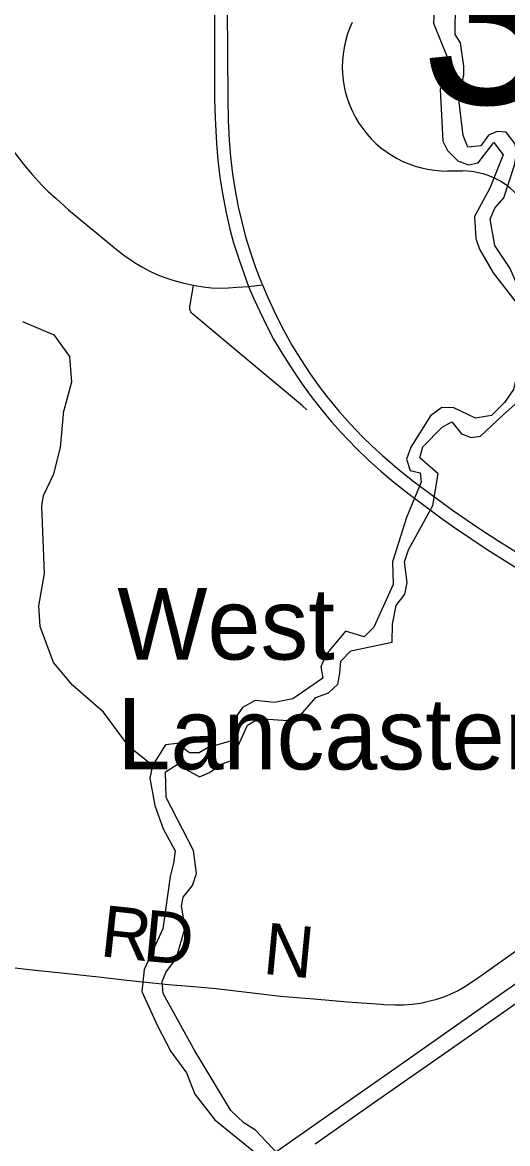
# Model space of a CAD drawing. Extents: x -49 to -8.2, y 9.4 to 23.5.
# Drawn here: x -41.395 to -41.126, y 17.238 to 17.858 of the extents above; entities that cross this region are included whole.
import ezdxf

# ---------------------------------------------------------------- set-up
doc = ezdxf.new("R2010")
doc.units = 0
for name, color, linetype in [('GM_X_County_Road', 7, 'Continuous'), ('GM_X_Interstate_Route', 7, 'Continuous'), ('GM_X_Major_River', 7, 'Continuous'), ('GM_X_Minor_River', 7, 'Continuous'), ('GM_X_State_Route', 7, 'Continuous'), ('GM_X_Township_Road', 7, 'Continuous'), ('GM_X_Township_Road_Text', 7, 'Continuous'), ('GM_X_Unincorporated_Text', 7, 'Continuous'), ('GM_X_US_Shield', 7, 'Continuous')]:
    doc.layers.add(name, color=color, linetype=linetype)

msp = doc.modelspace()

# ---------------------------------------------------------------- linework, layer by layer
at = {"layer": 'GM_X_County_Road'}
for points in [[(-41.40101, 17.78872), (-41.39439, 17.78007), (-41.38943, 17.77407), (-41.38416, 17.76832), (-41.38085, 17.76502), (-41.37623, 17.76084), (-41.36927, 17.75463), (-41.35971, 17.74666), (-41.35369, 17.74176), (-41.34292, 17.7328), (-41.338, 17.72897), (-41.33439, 17.72651)], [(-41.33439, 17.72651), (-41.33284, 17.72545), (-41.32882, 17.72304), (-41.32468, 17.72084), (-41.32041, 17.71889), (-41.31605, 17.71719), (-41.3116, 17.71573), (-41.30558, 17.71407), (-41.30025, 17.71289)], [(-41.30025, 17.71289), (-41.29948, 17.71272), (-41.29485, 17.71197), (-41.29019, 17.71151), (-41.28551, 17.71134), (-41.28081, 17.71143), (-41.27614, 17.71176), (-41.26968, 17.71222)], [(-41.26968, 17.71222), (-41.26206, 17.71303)]]:
    msp.add_lwpolyline(points, dxfattribs=at)
at = {"layer": 'GM_X_Interstate_Route'}
for points in [[(-41.23285, 17.23785), (-41.20004, 17.26087), (-41.16107, 17.28809), (-41.09894, 17.33152), (-41.07743, 17.34663), (-41.05165, 17.36473), (-41.02467, 17.38361), (-40.97838, 17.41607), (-40.95038, 17.43567), (-40.94996, 17.43597)], [(-41.25415, 17.23378), (-41.23997, 17.24376), (-41.21333, 17.26237), (-41.18692, 17.28076), (-41.12792, 17.32231), (-41.11945, 17.32829)]]:
    msp.add_lwpolyline(points, dxfattribs=at)
at = {"layer": 'GM_X_Major_River'}
for points in [[(-41.16654, 17.87659), (-41.16739, 17.85782), (-41.15973, 17.83863), (-41.1592, 17.83256), (-41.1638, 17.8212), (-41.16225, 17.79255), (-41.15962, 17.78742), (-41.15397, 17.7817), (-41.14812, 17.77959), (-41.14281, 17.7807), (-41.13405, 17.79185), (-41.12897, 17.78499), (-41.13626, 17.76663), (-41.14467, 17.75093), (-41.14398, 17.73879), (-41.14193, 17.7329), (-41.13442, 17.71978), (-41.12032, 17.70169), (-41.11547, 17.68839), (-41.11493, 17.68289), (-41.11992, 17.67001), (-41.12322, 17.65524), (-41.12817, 17.64805), (-41.13539, 17.64082)], [(-41.14125, 17.78998), (-41.14845, 17.78926), (-41.15106, 17.79572), (-41.15342, 17.81565), (-41.1507, 17.82929), (-41.15067, 17.83403), (-41.1525, 17.84694), (-41.1555, 17.85169), (-41.15522, 17.86857)], [(-41.12932, 17.64079), (-41.1187, 17.65028), (-41.11253, 17.6715), (-41.10263, 17.68264), (-41.10468, 17.68891), (-41.12027, 17.71098), (-41.12495, 17.7222), (-41.13359, 17.73495), (-41.13616, 17.74937), (-41.13348, 17.75562), (-41.12853, 17.76128), (-41.12257, 17.77927), (-41.12139, 17.78647), (-41.1225, 17.79122), (-41.1272, 17.7975), (-41.13212, 17.79791), (-41.13705, 17.79584), (-41.14125, 17.78998)], [(-41.13539, 17.64082), (-41.14422, 17.63929), (-41.15627, 17.6451), (-41.16273, 17.64521), (-41.16908, 17.64057), (-41.18, 17.62329), (-41.18239, 17.61668), (-41.1804, 17.61038), (-41.17472, 17.60915), (-41.17423, 17.60402), (-41.18234, 17.58441), (-41.19015, 17.55986), (-41.18978, 17.54733), (-41.20046, 17.52361), (-41.20584, 17.51836), (-41.21605, 17.52157), (-41.22691, 17.50847), (-41.22968, 17.50168), (-41.22864, 17.4954), (-41.24517, 17.48409), (-41.25547, 17.48199), (-41.26609, 17.48312), (-41.273, 17.47924), (-41.27728, 17.47324), (-41.27976, 17.46056), (-41.29217, 17.45717), (-41.29697, 17.45421), (-41.30249, 17.45411), (-41.30924, 17.45935), (-41.31572, 17.45851), (-41.32294, 17.44724), (-41.32438, 17.44024), (-41.32158, 17.42501), (-41.31704, 17.41221), (-41.31039, 17.39995), (-41.31126, 17.39313), (-41.31309, 17.38576), (-41.31717, 17.35679), (-41.32742, 17.33437), (-41.32876, 17.32205), (-41.32013, 17.30312), (-41.31276, 17.28895), (-41.30402, 17.27703), (-41.29945, 17.26538), (-41.28847, 17.25114), (-41.26505, 17.23207)], [(-41.23511, 17.21267), (-41.26594, 17.24545), (-41.27234, 17.24936), (-41.27945, 17.25631), (-41.29574, 17.28316), (-41.29926, 17.28891), (-41.31699, 17.3211), (-41.31746, 17.32756), (-41.31528, 17.33303), (-41.30984, 17.34015), (-41.30481, 17.35753), (-41.3069, 17.36933), (-41.30587, 17.37425), (-41.30082, 17.38081), (-41.29862, 17.38742), (-41.30013, 17.40016), (-41.31524, 17.42946), (-41.31577, 17.4437), (-41.30924, 17.44777), (-41.29681, 17.44092), (-41.29126, 17.44329), (-41.28433, 17.44811), (-41.27917, 17.44993), (-41.2703, 17.46952), (-41.26397, 17.47321), (-41.24821, 17.472), (-41.2423, 17.47361), (-41.23261, 17.48483), (-41.22553, 17.48737), (-41.22032, 17.49222), (-41.21928, 17.49828), (-41.2186, 17.50491), (-41.21319, 17.51052), (-41.19038, 17.51546), (-41.19014, 17.52532), (-41.18807, 17.53572), (-41.18322, 17.5419), (-41.18197, 17.54834), (-41.18349, 17.55994), (-41.1813, 17.56655), (-41.16779, 17.591), (-41.16484, 17.60861), (-41.17496, 17.61732), (-41.17334, 17.62355), (-41.16271, 17.63439), (-41.15734, 17.63733), (-41.15194, 17.6306), (-41.14665, 17.62861), (-41.14151, 17.62929), (-41.12932, 17.64079)]]:
    msp.add_lwpolyline(points, dxfattribs=at)
at = {"layer": 'GM_X_Minor_River'}
for points in [[(-41.39483, 17.69291), (-41.37745, 17.6855), (-41.36881, 17.67351), (-41.36775, 17.65928), (-41.37184, 17.64359)], [(-41.32294, 17.44724), (-41.33588, 17.45771), (-41.35002, 17.47673), (-41.36708, 17.49164), (-41.37771, 17.50415), (-41.38499, 17.52402), (-41.38576, 17.53542), (-41.38262, 17.5534), (-41.38411, 17.59063), (-41.38325, 17.5965), (-41.37754, 17.60855), (-41.3737, 17.62311), (-41.37184, 17.64359)]]:
    msp.add_lwpolyline(points, dxfattribs=at)
at = {"layer": 'GM_X_State_Route'}
for points in [[(-41.28885, 17.87207), (-41.28859, 17.85807), (-41.28855, 17.83139)], [(-41.28153, 17.86615), (-41.28127, 17.81647), (-41.281, 17.80404), (-41.28048, 17.79317), (-41.27973, 17.78387), (-41.27863, 17.77461), (-41.27719, 17.76538), (-41.27544, 17.75622), (-41.27372, 17.74863), (-41.27135, 17.73961), (-41.2691, 17.73216), (-41.26609, 17.72333), (-41.26273, 17.71462), (-41.26206, 17.71303), (-41.25908, 17.70603), (-41.25448, 17.69617), (-41.25025, 17.68785), (-41.24571, 17.6797), (-41.24087, 17.67172), (-41.23572, 17.66393), (-41.23121, 17.6576), (-41.22648, 17.65142), (-41.21956, 17.64302), (-41.21338, 17.63603), (-41.20696, 17.62926), (-41.2014, 17.62382), (-41.19564, 17.6186), (-41.18736, 17.61152), (-41.17889, 17.6047), (-41.16898, 17.5972), (-41.15636, 17.58813), (-41.14229, 17.57843), (-41.1319, 17.57161), (-41.0963, 17.54946)], [(-41.28855, 17.83139), (-41.28853, 17.81611), (-41.28825, 17.80525), (-41.28752, 17.79129), (-41.28677, 17.78201), (-41.28567, 17.77277), (-41.28421, 17.76358), (-41.28211, 17.75292), (-41.28001, 17.74385), (-41.27798, 17.73637), (-41.2752, 17.72749), (-41.27091, 17.71537), (-41.26968, 17.71222)], [(-41.26968, 17.71222), (-41.26688, 17.7053), (-41.26356, 17.69836), (-41.25952, 17.68996), (-41.25585, 17.68313), (-41.25111, 17.67512), (-41.24531, 17.66592), (-41.2401, 17.6582), (-41.23463, 17.65067), (-41.2289, 17.64332), (-41.22393, 17.63737), (-41.21873, 17.63161), (-41.21012, 17.62266), (-41.20345, 17.61616), (-41.19652, 17.60995), (-41.19177, 17.60598)], [(-41.19177, 17.60598), (-41.18937, 17.60398), (-41.1808, 17.59729), (-41.1634, 17.58422), (-41.15586, 17.57884)], [(-41.15586, 17.57884), (-41.15582, 17.57881), (-41.13777, 17.56667), (-41.09563, 17.54024), (-41.068, 17.52306)]]:
    msp.add_lwpolyline(points, dxfattribs=at)
at = {"layer": 'GM_X_Township_Road'}
for points in [[(-41.23755, 17.644), (-41.23989, 17.64608), (-41.27448, 17.67518), (-41.29724, 17.69414), (-41.30078, 17.69714), (-41.30127, 17.69767), (-41.30167, 17.69826), (-41.30196, 17.69887), (-41.30217, 17.69954), (-41.3022, 17.70023), (-41.30221, 17.70095), (-41.30096, 17.70859), (-41.30025, 17.71289)], [(-41.19492, 17.31499), (-41.18863, 17.31471), (-41.18397, 17.31474), (-41.17933, 17.31508), (-41.17471, 17.31574), (-41.17014, 17.31668), (-41.16566, 17.31792), (-41.16125, 17.31944), (-41.15694, 17.32121), (-41.15414, 17.32257), (-41.1501, 17.32489), (-41.14363, 17.32918), (-41.11187, 17.35154)], [(-41.40351, 17.33573), (-41.39117, 17.33428), (-41.36799, 17.33188), (-41.35101, 17.33002), (-41.33711, 17.32847), (-41.31394, 17.32599), (-41.30001, 17.32483), (-41.28763, 17.32371), (-41.26448, 17.32103), (-41.25213, 17.31961), (-41.23356, 17.31802), (-41.21498, 17.31647), (-41.19639, 17.31505), (-41.19492, 17.31499)]]:
    msp.add_lwpolyline(points, dxfattribs=at)
at = {"layer": 'GM_X_US_Shield'}
msp.add_line((-41.15954, 17.7761), (-41.1513, 17.7761), dxfattribs=at)
for centre, radius, start, end in [((-41.16019, 17.83377), 0.05768, 154.83192, 270.63826), ((-41.1513, 17.7349), 0.0412, 36.8699, 90)]:
    msp.add_arc(centre, radius, start, end, dxfattribs=at)

# ---------------------------------------------------------------- texts
at = {"layer": 'GM_X_Township_Road_Text'}
for s, rotation, p in [('R', 353.76239, (-41.35244, 17.34176)), ('D', 354.58345, (-41.32881, 17.33918)), ('N', 354.4784, (-41.26235, 17.332))]:
    msp.add_text(s, height=0.02841, rotation=rotation, dxfattribs=at).set_placement(p)
at = {"layer": 'GM_X_Unincorporated_Text'}
for s, p in [('West', (-41.34233, 17.5058)), ('Lancaster', (-41.34233, 17.44497))]:
    msp.add_text(s, height=0.039489, rotation=0.00001, dxfattribs=at).set_placement(p)
at = {"layer": 'GM_X_US_Shield'}
msp.add_text('35', height=0.098877, dxfattribs=at).set_placement((-41.17463, 17.81318))

doc.saveas('drawing.dxf')
